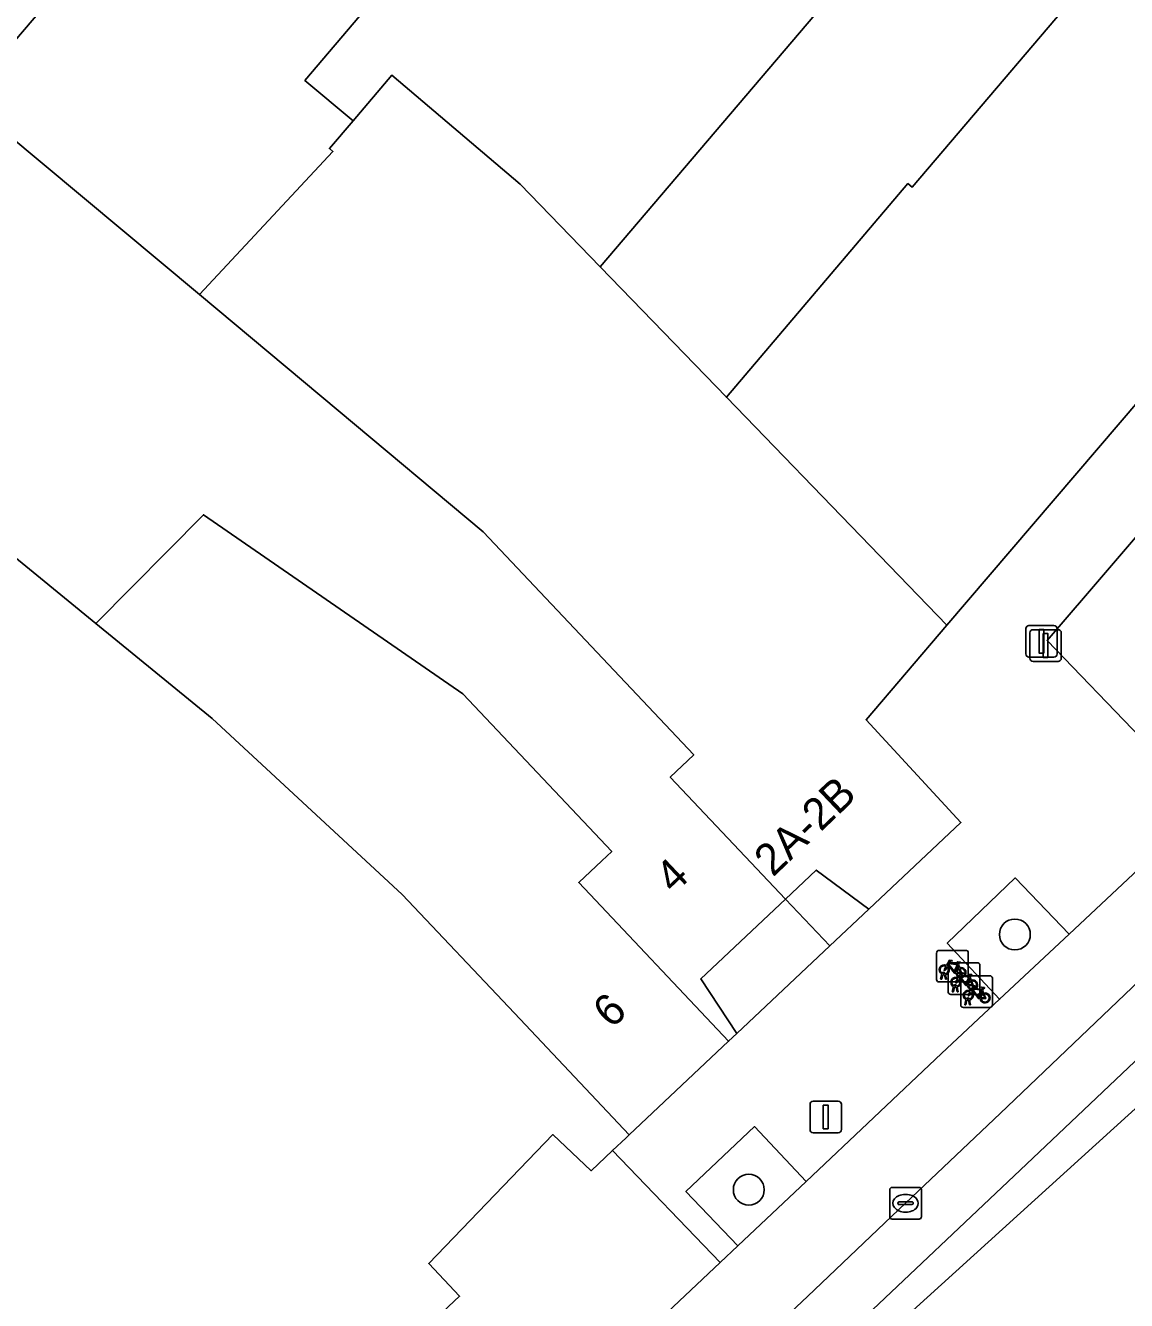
# Model space of a CAD drawing. Extents: x 162344 to 162869, y 381217 to 381818.
# Drawn here: x 162803 to 162837.77, y 381486.11 to 381526.4 of the extents above; entities that cross this region are included whole.
import ezdxf

# ---------------------------------------------------------------- set-up
doc = ezdxf.new("R2010")
doc.units = 0
for name, color, linetype in [('IMGEO_Boom', 7, 'Continuous'), ('IMGEO_Fietsenrek', 7, 'Continuous'), ('IMGEO_Groenvoorziening', 7, 'Continuous'), ('IMGEO_Kolk', 7, 'Continuous'), ('IMGEO_Lichtmast', 7, 'Continuous'), ('IMGEO_Pand', 7, 'Continuous'), ('IMGEO_Pand_nummerreeks', 7, 'Continuous'), ('IMGEO_Pand_overbouw', 7, 'Continuous'), ('IMGEO_Parkeervlak_open', 7, 'Continuous'), ('IMGEO_Rijbaan_lokaal_gesloten', 7, 'Continuous'), ('IMGEO_Rijbaan_lokaal_open', 7, 'Continuous'), ('IMGEO_Voetpad_open', 7, 'Continuous')]:
    doc.layers.add(name, color=color, linetype=linetype)

msp = doc.modelspace()

# ---------------------------------------------------------------- linework, layer by layer
at = {"layer": 'IMGEO_Boom'}
for centre in [(162834.247, 381497.672), (162825.844, 381489.606)]:
    msp.add_circle(centre, 0.489, dxfattribs=at)
at = {"layer": 'IMGEO_Fietsenrek'}
for p, q in [((162831.777, 381496.246), (162831.777, 381497.087)), ((162831.777, 381497.087), (162831.777, 381496.246)), ((162831.852, 381497.171), (162832.693, 381497.171)), ((162832.693, 381497.171), (162831.852, 381497.171)), ((162832.777, 381497.096), (162832.777, 381496.255)), ((162832.777, 381496.255), (162832.777, 381497.096)), ((162832.144, 381495.853), (162832.144, 381496.694)), ((162832.144, 381496.694), (162832.144, 381495.853)), ((162832.219, 381496.778), (162833.06, 381496.778)), ((162833.06, 381496.778), (162832.219, 381496.778)), ((162832.464, 381496.72), (162832.5, 381496.625)), ((162833.144, 381496.703), (162833.144, 381495.862)), ((162833.144, 381495.862), (162833.144, 381496.703)), ((162832.702, 381496.171), (162831.861, 381496.171)), ((162831.861, 381496.171), (162832.702, 381496.171)), ((162831.904, 381496.255), (162831.943, 381496.415)), ((162831.938, 381496.255), (162831.904, 381496.255)), ((162831.973, 381496.403), (162831.938, 381496.255)), ((162832.015, 381496.427), (162832.014, 381496.431)), ((162832.056, 381496.255), (162832.022, 381496.397)), ((162832.046, 381496.438), (162832.047, 381496.431)), ((162832.054, 381496.401), (162832.089, 381496.255)), ((162832.089, 381496.255), (162832.056, 381496.255)), ((162832.413, 381496.045), (162832.414, 381496.038)), ((162832.538, 381495.441), (162832.538, 381496.282)), ((162832.538, 381496.282), (162832.538, 381495.441)), ((162832.613, 381496.366), (162833.454, 381496.366)), ((162833.454, 381496.366), (162832.613, 381496.366)), ((162832.831, 381496.327), (162832.867, 381496.232)), ((162833.538, 381496.291), (162833.538, 381495.45)), ((162833.538, 381495.45), (162833.538, 381496.291)), ((162833.069, 381495.778), (162832.228, 381495.778)), ((162832.228, 381495.778), (162833.069, 381495.778)), ((162832.271, 381495.862), (162832.31, 381496.022)), ((162832.305, 381495.862), (162832.271, 381495.862)), ((162832.34, 381496.01), (162832.305, 381495.862)), ((162832.382, 381496.034), (162832.381, 381496.038)), ((162832.423, 381495.862), (162832.389, 381496.004)), ((162832.421, 381496.008), (162832.456, 381495.862)), ((162832.456, 381495.862), (162832.423, 381495.862)), ((162833.225, 381495.915), (162833.261, 381495.82)), ((162833.463, 381495.366), (162832.622, 381495.366)), ((162832.622, 381495.366), (162833.463, 381495.366)), ((162832.665, 381495.45), (162832.704, 381495.61)), ((162832.699, 381495.45), (162832.665, 381495.45)), ((162832.734, 381495.598), (162832.699, 381495.45)), ((162832.776, 381495.622), (162832.775, 381495.626)), ((162832.817, 381495.45), (162832.783, 381495.592)), ((162832.807, 381495.633), (162832.808, 381495.626)), ((162832.815, 381495.596), (162832.85, 381495.45)), ((162832.85, 381495.45), (162832.817, 381495.45))]:
    msp.add_line(p, q, dxfattribs=at)
for points in [[(162832.09, 381496.697), (162832.185, 381496.861), (162832.271, 381496.847), (162832.273, 381496.838), (162832.217, 381496.827), (162832.19, 381496.782), (162832.446, 381496.741)], [(162832.111, 381496.645), (162832.059, 381496.555), (162832.019, 381496.53), (162832.02, 381496.577), (162832.075, 381496.671)], [(162832.386, 381496.453), (162832.336, 381496.453), (162832.145, 381496.704), (162832.126, 381496.672)], [(162832.433, 381496.716), (162832.176, 381496.757), (162832.159, 381496.728), (162832.326, 381496.508), (162832.433, 381496.716)], [(162832.481, 381496.618), (162832.451, 381496.695), (162832.342, 381496.477), (162832.385, 381496.477)], [(162832.415, 381496.477), (162832.535, 381496.476), (162832.491, 381496.59)], [(162832.511, 381496.597), (162832.566, 381496.452), (162832.416, 381496.452)], [(162832.446, 381496.741), (162832.471, 381496.79), (162832.465, 381496.794), (162832.442, 381496.798), (162832.43, 381496.805), (162832.429, 381496.808), (162832.431, 381496.813), (162832.526, 381496.798), (162832.528, 381496.788), (162832.518, 381496.775), (162832.506, 381496.769), (162832.492, 381496.775), (162832.464, 381496.72)], [(162832.457, 381496.304), (162832.552, 381496.468), (162832.638, 381496.454), (162832.64, 381496.445), (162832.584, 381496.434), (162832.557, 381496.389), (162832.813, 381496.348)], [(162832.478, 381496.252), (162832.426, 381496.162), (162832.386, 381496.137), (162832.387, 381496.184), (162832.442, 381496.278)], [(162832.753, 381496.06), (162832.703, 381496.06), (162832.512, 381496.311), (162832.493, 381496.279)], [(162832.8, 381496.323), (162832.543, 381496.364), (162832.526, 381496.335), (162832.693, 381496.115), (162832.8, 381496.323)], [(162832.848, 381496.225), (162832.818, 381496.302), (162832.709, 381496.084), (162832.752, 381496.084)], [(162832.782, 381496.084), (162832.902, 381496.083), (162832.858, 381496.197)], [(162832.878, 381496.204), (162832.933, 381496.059), (162832.783, 381496.059)], [(162832.813, 381496.348), (162832.838, 381496.397), (162832.832, 381496.401), (162832.809, 381496.405), (162832.797, 381496.412), (162832.796, 381496.415), (162832.798, 381496.42), (162832.893, 381496.405), (162832.895, 381496.395), (162832.885, 381496.382), (162832.873, 381496.376), (162832.859, 381496.382), (162832.831, 381496.327)], [(162832.851, 381495.892), (162832.946, 381496.056), (162833.032, 381496.042), (162833.034, 381496.033), (162832.978, 381496.022), (162832.951, 381495.977), (162833.207, 381495.936)], [(162832.872, 381495.84), (162832.82, 381495.75), (162832.78, 381495.725), (162832.781, 381495.772), (162832.836, 381495.866)], [(162833.147, 381495.648), (162833.097, 381495.648), (162832.906, 381495.899), (162832.887, 381495.867)], [(162833.194, 381495.911), (162832.937, 381495.952), (162832.92, 381495.923), (162833.087, 381495.703), (162833.194, 381495.911)], [(162833.242, 381495.813), (162833.212, 381495.89), (162833.103, 381495.672), (162833.146, 381495.672)], [(162833.176, 381495.672), (162833.296, 381495.671), (162833.252, 381495.785)], [(162833.272, 381495.792), (162833.327, 381495.647), (162833.177, 381495.647)], [(162833.207, 381495.936), (162833.232, 381495.985), (162833.226, 381495.989), (162833.203, 381495.993), (162833.191, 381496), (162833.19, 381496.003), (162833.192, 381496.008), (162833.287, 381495.993), (162833.289, 381495.983), (162833.279, 381495.97), (162833.267, 381495.964), (162833.253, 381495.97), (162833.225, 381495.915)]]:
    msp.add_lwpolyline(points, dxfattribs=at)
for centre, radius, start, end in [((162831.855, 381497.093), 0.0779, 92.4484, 184.2845), ((162831.855, 381497.093), 0.0779, 92.4484, 184.2845), ((162832.699, 381497.093), 0.0779, 2.4484, 94.2845), ((162832.699, 381497.093), 0.0779, 2.4484, 94.2845), ((162832.017, 381496.556), 0.159, 62.6766, 242.1369), ((162832.017, 381496.556), 0.129, 63.3192, 238.903), ((162831.997, 381496.427), 0.0499, 12.8025, 158.6934), ((162831.997, 381496.427), 0.0174, 12.8025, 163.4502), ((162832.017, 381496.556), 0.129, 283.6043, 43.4302), ((162832.017, 381496.556), 0.159, 283.5766, 46.6042), ((162832.222, 381496.7), 0.0779, 92.4484, 184.2845), ((162832.222, 381496.7), 0.0779, 92.4484, 184.2845), ((162832.544, 381496.472), 0.159, 113.3408, 178.3217), ((162832.544, 381496.472), 0.159, 187.0065, 105.7708), ((162832.544, 381496.472), 0.129, 113.923, 177.9556), ((162832.544, 381496.472), 0.129, 188.6715, 104.5883), ((162833.066, 381496.7), 0.0779, 2.4484, 94.2845), ((162833.066, 381496.7), 0.0779, 2.4484, 94.2845), ((162831.855, 381496.249), 0.0779, 182.4484, 274.2845), ((162831.855, 381496.249), 0.0779, 182.4484, 274.2845), ((162832.017, 381496.556), 0.159, 253.9967, 271.7867), ((162832.017, 381496.556), 0.129, 253.415, 269.0204), ((162832.384, 381496.163), 0.159, 62.6766, 242.1369), ((162832.384, 381496.163), 0.129, 63.3192, 238.903), ((162832.364, 381496.034), 0.0499, 12.8025, 158.6934), ((162832.364, 381496.034), 0.0174, 12.8025, 163.4502), ((162832.384, 381496.163), 0.129, 283.6043, 43.4302), ((162832.384, 381496.163), 0.159, 283.5766, 46.6042), ((162832.616, 381496.288), 0.0779, 92.4484, 184.2845), ((162832.616, 381496.288), 0.0779, 92.4484, 184.2845), ((162832.699, 381496.249), 0.0779, 272.4484, 4.2845), ((162832.699, 381496.249), 0.0779, 272.4484, 4.2845), ((162832.911, 381496.079), 0.159, 113.3408, 178.3217), ((162832.911, 381496.079), 0.159, 187.0065, 105.7708), ((162832.911, 381496.079), 0.129, 113.923, 177.9556), ((162832.911, 381496.079), 0.129, 188.6715, 104.5883), ((162833.46, 381496.288), 0.0779, 2.4484, 94.2845), ((162833.46, 381496.288), 0.0779, 2.4484, 94.2845), ((162832.222, 381495.856), 0.0779, 182.4484, 274.2845), ((162832.222, 381495.856), 0.0779, 182.4484, 274.2845), ((162832.384, 381496.163), 0.159, 253.9967, 271.7867), ((162832.384, 381496.163), 0.129, 253.415, 269.0204), ((162832.778, 381495.751), 0.159, 62.6766, 242.1369), ((162832.778, 381495.751), 0.129, 63.3192, 238.903), ((162832.758, 381495.622), 0.0499, 12.8025, 158.6934), ((162832.758, 381495.622), 0.0174, 12.8025, 163.4502), ((162832.778, 381495.751), 0.129, 283.6043, 43.4302), ((162832.778, 381495.751), 0.159, 283.5766, 46.6042), ((162833.066, 381495.856), 0.0779, 272.4484, 4.2845), ((162833.066, 381495.856), 0.0779, 272.4484, 4.2845), ((162833.305, 381495.667), 0.159, 113.3408, 178.3217), ((162833.305, 381495.667), 0.159, 187.0065, 105.7708), ((162833.305, 381495.667), 0.129, 113.923, 177.9556), ((162833.305, 381495.667), 0.129, 188.6715, 104.5883), ((162832.616, 381495.444), 0.0779, 182.4484, 274.2845), ((162832.616, 381495.444), 0.0779, 182.4484, 274.2845), ((162832.778, 381495.751), 0.159, 253.9967, 271.7867), ((162832.778, 381495.751), 0.129, 253.415, 269.0204), ((162833.46, 381495.444), 0.0779, 272.4484, 4.2845), ((162833.46, 381495.444), 0.0779, 272.4484, 4.2845)]:
    msp.add_arc(centre, radius, start, end, dxfattribs=at)
at = {"layer": 'IMGEO_Groenvoorziening'}
for points in [[(162835.265, 381506.965), (162838.228, 381503.882), (162849.166, 381514.237), (162844.737, 381518.001)], [(162835.961, 381497.681), (162834.253, 381499.459), (162832.11, 381497.397), (162833.766, 381495.623)], [(162827.655, 381489.869), (162826.019, 381491.601), (162823.856, 381489.545), (162825.492, 381487.829)]]:
    msp.add_lwpolyline(points, close=True, dxfattribs=at)
at = {"layer": 'IMGEO_Kolk'}
for p, q in [((162830.295, 381488.752), (162830.295, 381489.604)), ((162830.37, 381489.678), (162831.222, 381489.678)), ((162831.296, 381489.604), (162831.296, 381488.752)), ((162830.597, 381489.221), (162830.995, 381489.221)), ((162830.783, 381489.458), (162830.808, 381489.458)), ((162830.554, 381489.172), (162830.554, 381489.184)), ((162830.992, 381489.135), (162830.594, 381489.135)), ((162830.806, 381488.898), (162830.781, 381488.898)), ((162831.038, 381489.184), (162831.038, 381489.172)), ((162831.222, 381488.678), (162830.37, 381488.678))]:
    msp.add_line(p, q, dxfattribs=at)
for points in [[(162830.295, 381488.752), (162830.295, 381489.604)], [(162830.37, 381489.678), (162831.222, 381489.678)], [(162831.296, 381489.604), (162831.296, 381488.752)], [(162831.222, 381488.678), (162830.37, 381488.678)]]:
    msp.add_lwpolyline(points, dxfattribs=at)
for centre, radius, start, end in [((162830.372, 381489.602), 0.0765, 91.552, 178.448), ((162830.372, 381489.602), 0.0765, 91.552, 178.448), ((162831.22, 381489.602), 0.0765, 1.552, 88.448), ((162831.22, 381489.602), 0.0765, 1.552, 88.448), ((162830.594, 381489.181), 0.0403, 85.8775, 175.7526), ((162830.999, 381489.183), 0.0386, 1.7309, 96.639), ((162830.591, 381489.171), 0.0366, 178.938, 274.7102), ((162830.995, 381489.178), 0.043, 264.8664, 352.4533), ((162830.372, 381488.754), 0.0765, 181.552, 268.448), ((162830.372, 381488.754), 0.0765, 181.552, 268.448), ((162831.22, 381488.754), 0.0765, 271.552, 358.448), ((162831.22, 381488.754), 0.0765, 271.552, 358.448)]:
    msp.add_arc(centre, radius, start, end, dxfattribs=at)
for centre, major_axis, ratio, start_param, end_param in [((162830.782, 381489.178), (-0.387, 0.002), 0.722429, 4.712389, 7.853982), ((162830.807, 381489.178), (-0.39, 0.002), 0.717154, 1.570796, 4.712389)]:
    msp.add_ellipse(centre, major_axis=major_axis, ratio=ratio, start_param=start_param, end_param=end_param, dxfattribs=at)
at = {"layer": 'IMGEO_Lichtmast'}
for p, q in [((162834.592, 381506.538), (162834.592, 381507.338)), ((162834.592, 381507.338), (162834.592, 381506.538)), ((162834.692, 381507.438), (162835.482, 381507.438)), ((162835.482, 381507.438), (162834.692, 381507.438)), ((162835.582, 381507.338), (162835.582, 381506.538)), ((162835.582, 381506.538), (162835.582, 381507.338)), ((162834.723, 381506.404), (162834.723, 381507.204)), ((162834.723, 381507.204), (162834.723, 381506.404)), ((162834.823, 381507.304), (162835.613, 381507.304)), ((162835.613, 381507.304), (162834.823, 381507.304)), ((162835.713, 381507.204), (162835.713, 381506.404)), ((162835.713, 381506.404), (162835.713, 381507.204)), ((162835.482, 381506.438), (162834.692, 381506.438)), ((162834.692, 381506.438), (162835.482, 381506.438)), ((162835.613, 381506.304), (162834.823, 381506.304)), ((162834.823, 381506.304), (162835.613, 381506.304)), ((162827.777, 381491.507), (162827.777, 381492.307)), ((162827.777, 381492.307), (162827.777, 381491.507)), ((162827.877, 381492.407), (162828.667, 381492.407)), ((162828.667, 381492.407), (162827.877, 381492.407)), ((162828.767, 381492.307), (162828.767, 381491.507)), ((162828.767, 381491.507), (162828.767, 381492.307)), ((162828.667, 381491.407), (162827.877, 381491.407)), ((162827.877, 381491.407), (162828.667, 381491.407))]:
    msp.add_line(p, q, dxfattribs=at)
for points in [[(162835.012, 381507.313), (162835.162, 381507.313), (162835.162, 381506.563), (162835.012, 381506.563), (162835.012, 381507.313)], [(162835.143, 381507.179), (162835.293, 381507.179), (162835.293, 381506.429), (162835.143, 381506.429), (162835.143, 381507.179)], [(162828.197, 381492.282), (162828.347, 381492.282), (162828.347, 381491.532), (162828.197, 381491.532), (162828.197, 381492.282)]]:
    msp.add_lwpolyline(points, dxfattribs=at)
for centre, start, end in [((162834.692, 381507.338), 90, 180), ((162834.692, 381507.338), 90, 180), ((162835.482, 381507.338), 0, 90), ((162835.482, 381507.338), 360, 90), ((162834.823, 381507.204), 90, 180), ((162834.823, 381507.204), 90, 180), ((162835.613, 381507.204), 0, 90), ((162835.613, 381507.204), 360, 90), ((162834.692, 381506.538), 180, 270), ((162834.692, 381506.538), 180, 270), ((162835.482, 381506.538), 270, 0), ((162835.482, 381506.538), 270, 0), ((162834.823, 381506.404), 180, 270), ((162834.823, 381506.404), 180, 270), ((162835.613, 381506.404), 270, 0), ((162835.613, 381506.404), 270, 0), ((162827.877, 381492.307), 90, 180), ((162827.877, 381492.307), 90, 180), ((162828.667, 381492.307), 0, 90), ((162828.667, 381492.307), 360, 90), ((162827.877, 381491.507), 180, 270), ((162827.877, 381491.507), 180, 270), ((162828.667, 381491.507), 270, 0), ((162828.667, 381491.507), 270, 0)]:
    msp.add_arc(centre, 0.1, start, end, dxfattribs=at)
at = {"layer": 'IMGEO_Pand'}
for points in [[(162817.998, 381543.688), (162818.905, 381544.742), (162813.298, 381549.512), (162808.46, 381543.819), (162802.645, 381536.74), (162800.467, 381534.147), (162796.986, 381529.991), (162799.612, 381527.76), (162802.29, 381525.485), (162805.161, 381528.866)], [(162824.698, 381539.819), (162820.872, 381543.085), (162819.613, 381541.599), (162807.133, 381527.19), (162805.161, 381528.866), (162802.29, 381525.485), (162801.088, 381524.07), (162808.488, 381517.895), (162812.709, 381522.415), (162812.598, 381522.509), (162813.346, 381523.389), (162811.823, 381524.665)], [(162833.01, 381532.723), (162824.698, 381539.819), (162811.823, 381524.665), (162813.346, 381523.389), (162814.567, 381524.826), (162818.623, 381521.38), (162821.151, 381518.767)], [(162837.476, 381528.911), (162833.01, 381532.723), (162821.151, 381518.767), (162825.134, 381514.651), (162830.872, 381521.405), (162831.004, 381521.293)], [(162837.476, 381528.911), (162831.004, 381521.293), (162830.872, 381521.405), (162825.134, 381514.651), (162829.673, 381509.959), (162832.103, 381507.448), (162844.977, 381522.508)], [(162829.673, 381509.959), (162825.134, 381514.651), (162821.151, 381518.767), (162818.623, 381521.38), (162814.567, 381524.826), (162813.346, 381523.389), (162812.598, 381522.509), (162812.709, 381522.415), (162808.488, 381517.895), (162812.874, 381514.228), (162817.454, 381510.4), (162824.106, 381503.349), (162823.361, 381502.646), (162827.002, 381498.792), (162827.976, 381499.71), (162829.636, 381498.474), (162832.546, 381501.214), (162829.548, 381504.46), (162832.103, 381507.448)], [(162817.454, 381510.4), (162812.874, 381514.228), (162808.488, 381517.895), (162801.088, 381524.07), (162796.153, 381519.447), (162794.525, 381517.894), (162801.252, 381510.74), (162805.218, 381507.501), (162808.614, 381510.936), (162816.812, 381505.278), (162821.516, 381500.296), (162821.202, 381500), (162820.474, 381499.313), (162825.204, 381494.3), (162825.465, 381494.546), (162824.324, 381496.266), (162827.002, 381498.792), (162823.361, 381502.646), (162824.106, 381503.349)], [(162816.812, 381505.278), (162808.614, 381510.936), (162805.218, 381507.501), (162808.894, 381504.5), (162813.749, 381500), (162814.892, 381498.941), (162818.438, 381495.183), (162822.062, 381491.34), (162825.204, 381494.3), (162820.474, 381499.313), (162821.202, 381500), (162821.516, 381500.296)]]:
    msp.add_lwpolyline(points, close=True, dxfattribs=at)
msp.add_lwpolyline([(162802.337, 381472.727), (162816.707, 381486.237), (162815.735, 381487.272), (162819.658, 381491.351), (162820.86, 381490.207), (162821.538, 381490.847), (162821.967, 381491.251), (162822.062, 381491.34), (162818.438, 381495.183), (162814.892, 381498.941), (162813.749, 381500), (162808.894, 381504.5), (162805.218, 381507.501), (162801.252, 381510.74)], dxfattribs=at)
at = {"layer": 'IMGEO_Pand_overbouw'}
for points in [[(162827.976, 381499.71), (162827.002, 381498.792), (162828.401, 381497.311), (162829.636, 381498.474)], [(162828.401, 381497.311), (162827.002, 381498.792), (162824.324, 381496.266), (162825.465, 381494.546)]]:
    msp.add_lwpolyline(points, close=True, dxfattribs=at)
at = {"layer": 'IMGEO_Parkeervlak_open'}
msp.add_lwpolyline([(162833.781, 381492.012), (162842.125, 381499.976), (162840.352, 381501.799), (162835.961, 381497.681), (162833.766, 381495.623), (162831.935, 381493.906), (162827.655, 381489.869), (162825.492, 381487.829), (162824.936, 381487.305), (162811.037, 381474.196), (162810.029, 381473.245), (162810.102, 381473.169), (162811.862, 381471.343), (162814.764, 381474.059), (162827.711, 381486.247), (162830.796, 381489.178)], close=True, dxfattribs=at)
at = {"layer": 'IMGEO_Rijbaan_lokaal_gesloten'}
msp.add_lwpolyline([(162853.478, 381506.159), (162854.238, 381506.848), (162851.724, 381509.508), (162848.454, 381506.011), (162847.319, 381504.969), (162846.835, 381504.477), (162846.625, 381504.264), (162846.067, 381503.735), (162842.125, 381499.976), (162833.781, 381492.012), (162830.796, 381489.178), (162827.711, 381486.247), (162814.764, 381474.059), (162811.862, 381471.343), (162808.668, 381468.353), (162798.45, 381458.708), (162797.325, 381457.652), (162796.845, 381457.203), (162798.029, 381455.968), (162828.984, 381485.085), (162834.615, 381490.41), (162844.258, 381499.558)], dxfattribs=at)
at = {"layer": 'IMGEO_Rijbaan_lokaal_open'}
for points in [[(162797.947, 381455.225), (162805.516, 381462.64), (162853.478, 381506.159), (162852.183, 381507.468)], [(162844.258, 381499.558), (162834.615, 381490.41), (162828.984, 381485.085), (162798.029, 381455.968), (162796.845, 381457.203), (162796.428, 381456.813), (162797.947, 381455.225)]]:
    msp.add_lwpolyline(points, dxfattribs=at)
at = {"layer": 'IMGEO_Voetpad_open'}
for points in [[(162844.977, 381522.508), (162832.103, 381507.448), (162829.548, 381504.46), (162832.546, 381501.214), (162829.636, 381498.474), (162827.976, 381499.71), (162827.002, 381498.792), (162824.324, 381496.266), (162825.465, 381494.546), (162825.204, 381494.3), (162822.062, 381491.34), (162821.967, 381491.251), (162821.538, 381490.847), (162824.936, 381487.305), (162825.492, 381487.829), (162823.856, 381489.545), (162826.019, 381491.601), (162827.655, 381489.869), (162831.935, 381493.906), (162833.766, 381495.623), (162832.11, 381497.397), (162834.253, 381499.459), (162835.961, 381497.681), (162840.352, 381501.799)], [(162807.225, 381473.889), (162809.385, 381475.939), (162811.037, 381474.196), (162824.936, 381487.305), (162821.538, 381490.847), (162820.86, 381490.207), (162819.658, 381491.351), (162815.735, 381487.272), (162816.707, 381486.237), (162802.337, 381472.727), (162800.142, 381472.494), (162800.792, 381471.861), (162795.481, 381466.405), (162794.926, 381465.598), (162762.117, 381434.713), (162761.099, 381432.973), (162761.657, 381432.397)]]:
    msp.add_lwpolyline(points, dxfattribs=at)
msp.add_lwpolyline([(162838.228, 381503.882), (162835.265, 381506.965), (162844.737, 381518.001), (162849.166, 381514.237)], close=True, dxfattribs=at)

# ---------------------------------------------------------------- texts
at = {"layer": 'IMGEO_Pand_nummerreeks'}
for s, rotation, p in [('2A-2B', 43.5734, (162826.605, 381499.468)), ('4', 43.3271, (162823.476, 381498.93)), ('6', 43.3099, (162821.509, 381494.671))]:
    msp.add_text(s, height=1, rotation=rotation, dxfattribs=at).set_placement(p)

doc.saveas('drawing.dxf')
